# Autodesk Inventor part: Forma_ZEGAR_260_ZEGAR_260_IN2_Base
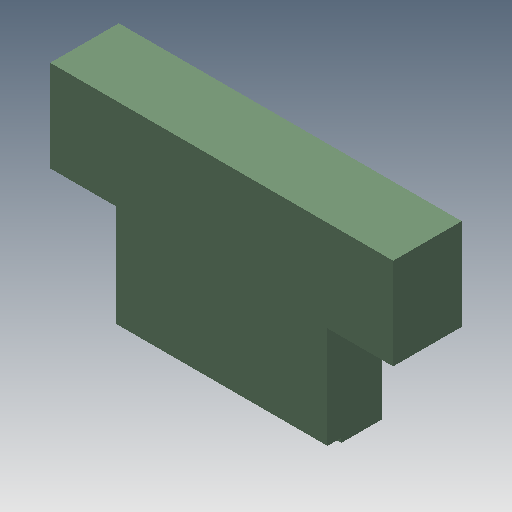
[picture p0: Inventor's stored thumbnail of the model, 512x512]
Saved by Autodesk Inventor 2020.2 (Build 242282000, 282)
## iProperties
Created: 2015-01
Part Number: Forma_ZEGAR_260_ZEGAR_260_IN2_Base
Material: Ogólny
Document SubType Name: Modeling
Designer: F.Stasiak
Density: 1 g/cm^3
Appearance: Domyślna
Catalog Web Link: www.expertbooks.pl
Manager: www.cadconsulting.pl
Company: Fabian Stasiak CAD Consulting
Author: F.Stasiak
Subject: Zbiór ćwiczeń. Autodesk Inventor 2020. Kurs Professional
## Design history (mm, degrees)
node "Forma_ZEGAR_260_ZEGAR_260_MP"
feature "Bryła15::Forma_ZEGAR_260_ZEGAR_260_MP"
tag "Bryła wyprowadzona1"
node "Bryła1"
feature "Forma_ZEGAR_260_ZEGAR_260_MP_Bodies"
